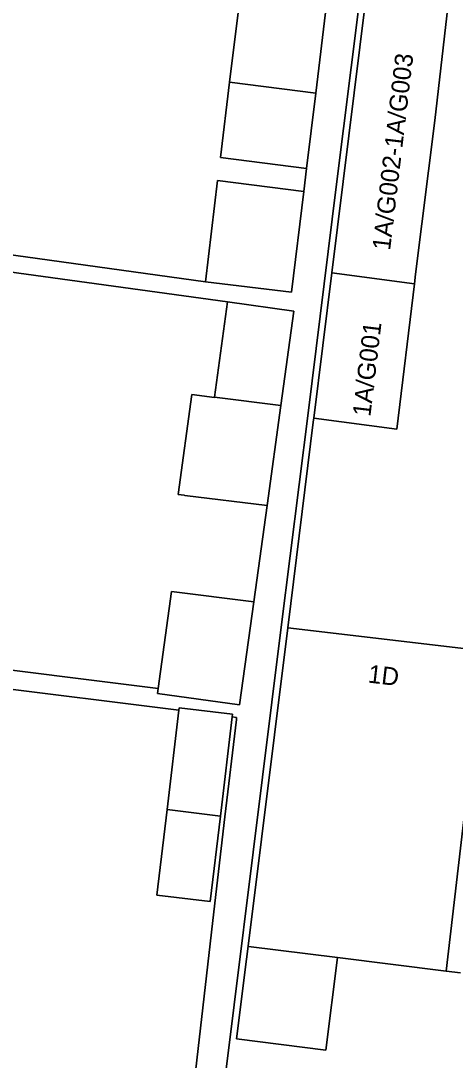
# Model space of a CAD drawing. Extents: x 161692 to 162379, y 380760 to 381678.
# Drawn here: x 162249.3 to 162273.5, y 381258.9 to 381316.7 of the extents above; entities that cross this region are included whole.
import ezdxf

# ---------------------------------------------------------------- set-up
doc = ezdxf.new("R2010")
doc.units = 0
for name, color, linetype in [('IMGEO_Erf', 7, 'Continuous'), ('IMGEO_Pand', 7, 'Continuous'), ('IMGEO_Pand_nummerreeks', 7, 'Continuous'), ('IMGEO_Voetpad_open', 7, 'Continuous')]:
    doc.layers.add(name, color=color, linetype=linetype)

msp = doc.modelspace()

# ---------------------------------------------------------------- linework, layer by layer
at = {"layer": 'IMGEO_Erf'}
for points in [[(162271.787, 381347.044), (162266.831, 381307.5), (162265.259, 381294.924), (162263.772, 381283.024), (162259.583, 381249.511)], [(162273.75, 381263.809), (162272.937, 381263.902), (162266.9, 381264.655), (162266.258, 381259.504), (162261.283, 381260.124), (162261.835, 381264.56), (162261.924, 381265.275), (162264.127, 381282.983), (162265.567, 381294.564), (162265.577, 381294.639), (162266.582, 381302.726), (162268.777, 381320.363)], [(162242.396, 381318.311), (162242.067, 381315.664), (162237.767, 381316.199), (162237.44, 381313.57), (162242.886, 381312.892), (162242.935, 381313.289), (162244.992, 381313.033), (162245.79, 381312.032), (162245.498, 381309.679), (162246.595, 381309.543), (162246.28, 381307.016), (162242.218, 381307.522), (162239.982, 381307.801), (162239.631, 381304.981), (162259.547, 381302.233), (162260.23, 381307.853), (162265.026, 381307.247), (162265.182, 381308.528), (162260.386, 381309.134), (162260.895, 381313.321), (162261.495, 381318.25)], [(162233.496, 381282.545), (162256.921, 381279.617), (162257.664, 381285.005), (162262.24, 381284.436), (162262.977, 381289.783), (162258.401, 381290.352), (162258.366, 381290.357), (162258.03, 381290.403), (162258.796, 381295.961), (162260.047, 381295.789), (162260.049, 381295.804), (162260.78, 381301.109), (162241.734, 381303.732)], [(162258.536, 381254.262), (162260.014, 381267.198), (162260.634, 381272.474), (162261.27, 381277.887), (162261.283, 381278), (162261.045, 381278.03), (162260.385, 381272.505), (162259.818, 381267.768), (162256.844, 381268.118), (162257.413, 381272.875), (162258.074, 381278.401), (162236.647, 381281.081)]]:
    msp.add_lwpolyline(points, dxfattribs=at)
at = {"layer": 'IMGEO_Pand'}
for points in [[(162273.325, 381319.949), (162272.813, 381320.011), (162268.799, 381320.541), (162268.777, 381320.363), (162266.582, 381302.726), (162271.178, 381302.121), (162271.243, 381302.657), (162272.323, 381311.201)], [(162260.895, 381313.321), (162265.692, 381312.724), (162266.294, 381317.666), (162261.495, 381318.25)], [(162265.692, 381312.724), (162260.895, 381313.321), (162260.386, 381309.134), (162265.182, 381308.528)], [(162265.026, 381307.247), (162260.23, 381307.853), (162259.547, 381302.233), (162264.345, 381301.648)], [(162271.178, 381302.121), (162266.582, 381302.726), (162265.577, 381294.639), (162270.197, 381294.026)], [(162263.744, 381295.344), (162264.468, 381300.601), (162260.78, 381301.109), (162260.049, 381295.804)], [(162263.744, 381295.344), (162260.049, 381295.804), (162260.047, 381295.789), (162258.796, 381295.961), (162258.03, 381290.403), (162258.366, 381290.357), (162258.401, 381290.352), (162262.977, 381289.783)], [(162262.24, 381284.436), (162257.664, 381285.005), (162256.921, 381279.617), (162256.882, 381279.334), (162261.45, 381278.705)], [(162275.022, 381281.707), (162264.127, 381282.983), (162261.924, 381265.275), (162261.954, 381265.271), (162266.9, 381264.655), (162272.937, 381263.902)], [(162261.045, 381278.03), (162261.064, 381278.185), (162258.09, 381278.534), (162258.074, 381278.401), (162257.413, 381272.875), (162260.385, 381272.505)], [(162260.385, 381272.505), (162257.413, 381272.875), (162256.844, 381268.118), (162259.818, 381267.768)], [(162266.9, 381264.655), (162261.954, 381265.271), (162261.924, 381265.275), (162261.835, 381264.56), (162261.283, 381260.124), (162266.258, 381259.504)]]:
    msp.add_lwpolyline(points, close=True, dxfattribs=at)
at = {"layer": 'IMGEO_Voetpad_open'}
for points in [[(162259.583, 381249.511), (162263.772, 381283.024), (162265.259, 381294.924), (162266.831, 381307.5), (162271.787, 381347.044)], [(162273.325, 381319.949), (162272.323, 381311.201), (162271.243, 381302.657), (162271.178, 381302.121), (162270.197, 381294.026), (162265.577, 381294.639), (162265.567, 381294.564), (162264.127, 381282.983), (162275.022, 381281.707), (162272.937, 381263.902), (162273.75, 381263.809)], [(162266.294, 381317.666), (162265.692, 381312.724), (162265.182, 381308.528), (162265.026, 381307.247), (162264.345, 381301.648), (162259.547, 381302.233), (162239.631, 381304.981)], [(162241.734, 381303.732), (162260.78, 381301.109), (162264.468, 381300.601), (162263.744, 381295.344), (162262.977, 381289.783), (162262.24, 381284.436), (162261.45, 381278.705), (162256.882, 381279.334), (162256.921, 381279.617), (162233.496, 381282.545)], [(162236.647, 381281.081), (162258.074, 381278.401), (162258.09, 381278.534), (162261.064, 381278.185), (162261.045, 381278.03), (162261.283, 381278), (162261.27, 381277.887), (162260.634, 381272.474), (162260.014, 381267.198), (162258.536, 381254.262)]]:
    msp.add_lwpolyline(points, dxfattribs=at)

# ---------------------------------------------------------------- texts
at = {"layer": 'IMGEO_Pand_nummerreeks'}
for s, rotation, p in [('1A/G002-1A/G003', 83.21639, (162269.825, 381303.94)), ('1A/G001', 83.21639, (162268.727, 381294.702)), ('1D', 353.31931, (162268.563, 381279.946))]:
    msp.add_text(s, height=1, rotation=rotation, dxfattribs=at).set_placement(p)

doc.saveas('drawing.dxf')
